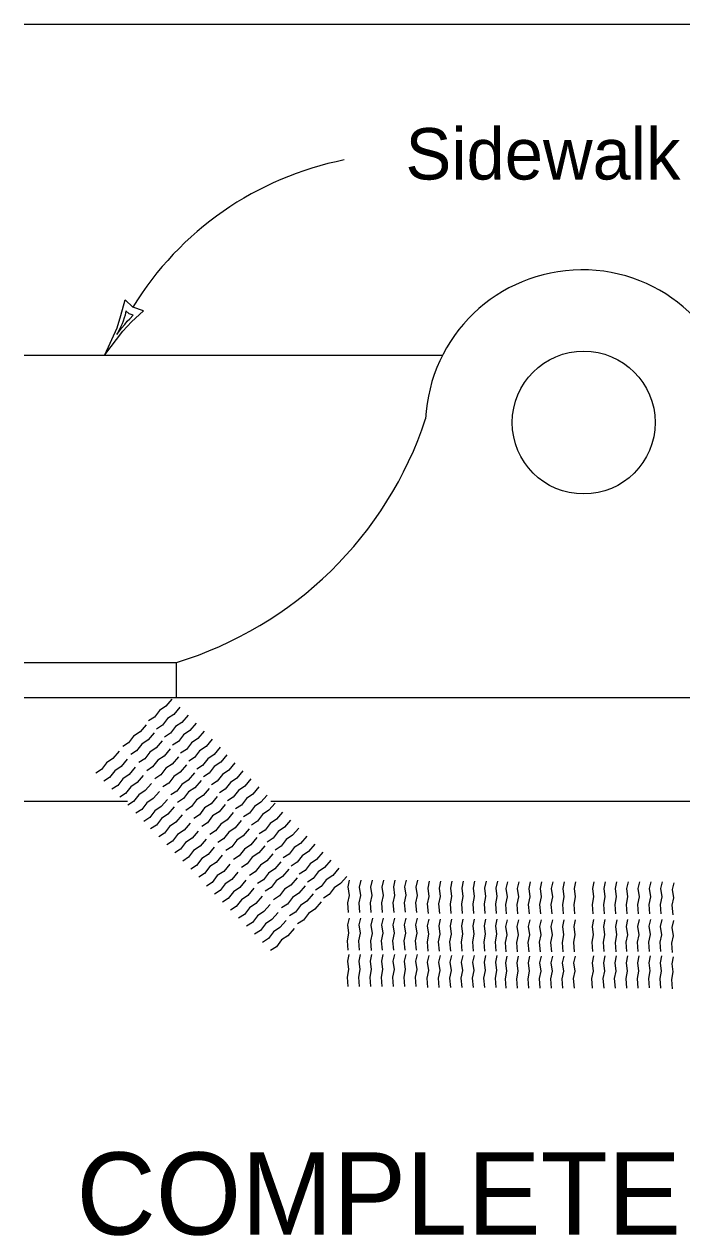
# Model space of a CAD drawing. Extents: x 539344 to 540004, y 1574686 to 1575110.
# Drawn here: x 539790.6 to 539822.6, y 1574749.8 to 1574808.7 of the extents above; entities that cross this region are included whole.
import ezdxf

# ---------------------------------------------------------------- set-up
doc = ezdxf.new("R2010")
doc.units = 0
doc.layers.add('Default', color=7, linetype='Continuous')

msp = doc.modelspace()

# ---------------------------------------------------------------- linework, layer by layer
at = {"layer": 'Default'}
for p, q in [((539790.564, 1574808.736), (539848.567, 1574808.736)), ((539795.852, 1574794.98), (539795.47, 1574795.324)), ((539796.366, 1574794.792), (539795.852, 1574794.98)), ((539790.564, 1574792.644), (539810.928, 1574792.644)), ((539790.564, 1574777.696), (539797.978, 1574777.696)), ((539797.978, 1574775.988), (539797.978, 1574777.696)), ((539790.564, 1574775.988), (539797.978, 1574775.988)), ((539797.978, 1574775.988), (539837.69, 1574775.988)), ((539790.564, 1574770.948), (539795.588, 1574770.948)), ((539802.566, 1574770.948), (539832.96, 1574770.948))]:
    msp.add_line(p, q, dxfattribs=at)
for points in [[(539794.492, 1574792.66), (539795.088, 1574793.974), (539795.272, 1574794.568), (539795.47, 1574795.324)], [(539794.492, 1574792.66), (539795.358, 1574793.814), (539795.792, 1574794.262), (539796.366, 1574794.792)], [(539795.074, 1574793.644), (539795.298, 1574793.954), (539795.456, 1574794.134), (539795.578, 1574794.296), (539795.698, 1574794.408), (539795.866, 1574794.582), (539795.668, 1574794.646), (539795.508, 1574794.794), (539795.478, 1574794.59), (539795.434, 1574794.448), (539795.372, 1574794.3), (539795.328, 1574794.158), (539795.268, 1574794.036), (539795.208, 1574793.89), (539795.074, 1574793.644)], [(539797.752, 1574775.908), (539797.454, 1574775.558), (539797.142, 1574775.35), (539796.896, 1574775.024), (539796.61, 1574774.844)], [(539798.144, 1574775.518), (539797.846, 1574775.166), (539797.536, 1574774.962), (539797.288, 1574774.634), (539797.002, 1574774.454)], [(539798.538, 1574775.128), (539798.238, 1574774.778), (539797.928, 1574774.57), (539797.682, 1574774.244), (539797.396, 1574774.062)], [(539796.5, 1574774.662), (539796.2, 1574774.312), (539795.888, 1574774.106), (539795.64, 1574773.78), (539795.356, 1574773.598)], [(539798.926, 1574774.736), (539798.626, 1574774.384), (539798.316, 1574774.178), (539798.068, 1574773.852), (539797.784, 1574773.672)], [(539796.892, 1574774.274), (539796.592, 1574773.922), (539796.28, 1574773.716), (539796.034, 1574773.39), (539795.75, 1574773.208)], [(539799.318, 1574774.346), (539799.02, 1574773.992), (539798.71, 1574773.788), (539798.46, 1574773.462), (539798.176, 1574773.28)], [(539799.71, 1574773.954), (539799.412, 1574773.602), (539799.1, 1574773.398), (539798.852, 1574773.072), (539798.568, 1574772.89)], [(539795.184, 1574773.372), (539794.884, 1574773.022), (539794.572, 1574772.814), (539794.326, 1574772.488), (539794.042, 1574772.308)], [(539797.282, 1574773.882), (539796.986, 1574773.532), (539796.674, 1574773.324), (539796.426, 1574772.998), (539796.142, 1574772.818)], [(539797.672, 1574773.492), (539797.372, 1574773.14), (539797.06, 1574772.932), (539796.814, 1574772.608), (539796.532, 1574772.426)], [(539800.102, 1574773.564), (539799.802, 1574773.212), (539799.492, 1574773.008), (539799.244, 1574772.68), (539798.96, 1574772.498)], [(539795.576, 1574772.984), (539795.276, 1574772.634), (539794.966, 1574772.426), (539794.718, 1574772.098), (539794.434, 1574771.918)], [(539798.064, 1574773.102), (539797.766, 1574772.75), (539797.454, 1574772.542), (539797.206, 1574772.218), (539796.922, 1574772.036)], [(539798.456, 1574772.71), (539798.156, 1574772.36), (539797.846, 1574772.15), (539797.598, 1574771.826), (539797.314, 1574771.644)], [(539800.426, 1574773.196), (539800.128, 1574772.848), (539799.814, 1574772.638), (539799.568, 1574772.312), (539799.282, 1574772.132)], [(539800.818, 1574772.806), (539800.52, 1574772.456), (539800.208, 1574772.248), (539799.96, 1574771.924), (539799.674, 1574771.74)], [(539795.968, 1574772.592), (539795.672, 1574772.242), (539795.36, 1574772.034), (539795.112, 1574771.708), (539794.826, 1574771.526)], [(539796.358, 1574772.2), (539796.058, 1574771.85), (539795.748, 1574771.644), (539795.5, 1574771.318), (539795.214, 1574771.136)], [(539798.846, 1574772.32), (539798.548, 1574771.968), (539798.238, 1574771.76), (539797.99, 1574771.434), (539797.706, 1574771.252)], [(539801.208, 1574772.416), (539800.91, 1574772.066), (539800.596, 1574771.856), (539800.35, 1574771.532), (539800.064, 1574771.35)], [(539796.75, 1574771.81), (539796.45, 1574771.46), (539796.14, 1574771.254), (539795.89, 1574770.926), (539795.606, 1574770.746)], [(539799.174, 1574771.952), (539798.874, 1574771.6), (539798.562, 1574771.396), (539798.314, 1574771.068), (539798.03, 1574770.886)], [(539799.566, 1574771.562), (539799.266, 1574771.212), (539798.952, 1574771.004), (539798.706, 1574770.678), (539798.422, 1574770.496)], [(539801.598, 1574772.026), (539801.3, 1574771.676), (539800.988, 1574771.466), (539800.74, 1574771.142), (539800.456, 1574770.958)], [(539801.988, 1574771.634), (539801.692, 1574771.284), (539801.38, 1574771.074), (539801.13, 1574770.75), (539800.848, 1574770.568)], [(539797.142, 1574771.418), (539796.844, 1574771.07), (539796.532, 1574770.862), (539796.282, 1574770.536), (539795.998, 1574770.354)], [(539797.534, 1574771.028), (539797.236, 1574770.678), (539796.924, 1574770.47), (539796.674, 1574770.144), (539796.39, 1574769.962)], [(539799.954, 1574771.172), (539799.656, 1574770.818), (539799.344, 1574770.614), (539799.096, 1574770.286), (539798.812, 1574770.104)], [(539802.382, 1574771.242), (539802.084, 1574770.892), (539801.77, 1574770.682), (539801.524, 1574770.358), (539801.238, 1574770.176)], [(539797.858, 1574770.662), (539797.56, 1574770.312), (539797.248, 1574770.104), (539797, 1574769.778), (539796.714, 1574769.596)], [(539800.344, 1574770.782), (539800.046, 1574770.428), (539799.734, 1574770.224), (539799.486, 1574769.896), (539799.202, 1574769.714)], [(539800.736, 1574770.39), (539800.438, 1574770.036), (539800.126, 1574769.832), (539799.878, 1574769.504), (539799.594, 1574769.324)], [(539802.772, 1574770.852), (539802.472, 1574770.502), (539802.16, 1574770.292), (539801.912, 1574769.968), (539801.628, 1574769.784)], [(539803.14, 1574770.416), (539802.84, 1574770.064), (539802.53, 1574769.858), (539802.284, 1574769.532), (539801.998, 1574769.35)], [(539798.25, 1574770.272), (539797.95, 1574769.92), (539797.64, 1574769.714), (539797.392, 1574769.388), (539797.108, 1574769.208)], [(539798.638, 1574769.88), (539798.342, 1574769.528), (539798.03, 1574769.322), (539797.782, 1574768.996), (539797.498, 1574768.814)], [(539801.128, 1574769.998), (539800.83, 1574769.644), (539800.518, 1574769.44), (539800.27, 1574769.112), (539799.986, 1574768.93)], [(539803.53, 1574770.024), (539803.228, 1574769.672), (539802.92, 1574769.466), (539802.674, 1574769.14), (539802.386, 1574768.958)], [(539799.03, 1574769.49), (539798.732, 1574769.138), (539798.42, 1574768.932), (539798.172, 1574768.606), (539797.886, 1574768.426)], [(539801.516, 1574769.606), (539801.218, 1574769.256), (539800.906, 1574769.048), (539800.66, 1574768.722), (539800.374, 1574768.542)], [(539803.922, 1574769.632), (539803.62, 1574769.284), (539803.31, 1574769.076), (539803.062, 1574768.752), (539802.776, 1574768.568)], [(539804.312, 1574769.244), (539804.012, 1574768.892), (539803.702, 1574768.686), (539803.456, 1574768.36), (539803.17, 1574768.18)], [(539799.422, 1574769.098), (539799.122, 1574768.748), (539798.81, 1574768.54), (539798.564, 1574768.216), (539798.278, 1574768.034)], [(539799.814, 1574768.706), (539799.516, 1574768.356), (539799.204, 1574768.148), (539798.956, 1574767.822), (539798.67, 1574767.64)], [(539801.886, 1574769.17), (539801.59, 1574768.82), (539801.276, 1574768.612), (539801.03, 1574768.286), (539800.744, 1574768.104)], [(539802.274, 1574768.778), (539801.976, 1574768.426), (539801.662, 1574768.22), (539801.416, 1574767.894), (539801.132, 1574767.714)], [(539804.704, 1574768.852), (539804.404, 1574768.5), (539804.094, 1574768.292), (539803.846, 1574767.97), (539803.562, 1574767.786)], [(539800.202, 1574768.316), (539799.902, 1574767.964), (539799.59, 1574767.76), (539799.344, 1574767.432), (539799.06, 1574767.25)], [(539802.666, 1574768.39), (539802.366, 1574768.038), (539802.056, 1574767.832), (539801.808, 1574767.504), (539801.524, 1574767.322)], [(539803.056, 1574767.998), (539802.76, 1574767.65), (539802.448, 1574767.44), (539802.202, 1574767.114), (539801.916, 1574766.932)], [(539805.096, 1574768.46), (539804.796, 1574768.11), (539804.486, 1574767.902), (539804.238, 1574767.578), (539803.952, 1574767.396)], [(539805.484, 1574768.07), (539805.184, 1574767.718), (539804.874, 1574767.512), (539804.626, 1574767.188), (539804.342, 1574767.004)], [(539800.572, 1574767.88), (539800.274, 1574767.53), (539799.96, 1574767.322), (539799.714, 1574766.996), (539799.428, 1574766.814)], [(539800.958, 1574767.488), (539800.662, 1574767.138), (539800.35, 1574766.93), (539800.102, 1574766.604), (539799.818, 1574766.422)], [(539803.434, 1574767.634), (539803.136, 1574767.284), (539802.822, 1574767.076), (539802.576, 1574766.75), (539802.292, 1574766.568)], [(539805.876, 1574767.678), (539805.576, 1574767.326), (539805.266, 1574767.118), (539805.018, 1574766.796), (539804.732, 1574766.614)], [(539801.352, 1574767.1), (539801.054, 1574766.748), (539800.742, 1574766.54), (539800.492, 1574766.214), (539800.208, 1574766.032)], [(539803.84, 1574767.216), (539803.542, 1574766.866), (539803.23, 1574766.658), (539802.984, 1574766.332), (539802.698, 1574766.148)], [(539804.23, 1574766.824), (539803.93, 1574766.474), (539803.62, 1574766.266), (539803.372, 1574765.938), (539803.088, 1574765.758)], [(539806.264, 1574767.286), (539805.964, 1574766.936), (539805.654, 1574766.73), (539805.406, 1574766.404), (539805.122, 1574766.22)], [(539806.348, 1574765.536), (539806.312, 1574765.996), (539806.386, 1574766.362), (539806.33, 1574766.77), (539806.402, 1574767.098)], [(539806.902, 1574765.534), (539806.864, 1574765.994), (539806.938, 1574766.362), (539806.884, 1574766.766), (539806.956, 1574767.098)], [(539807.454, 1574765.534), (539807.416, 1574765.994), (539807.492, 1574766.362), (539807.436, 1574766.766), (539807.51, 1574767.098)], [(539808.008, 1574765.534), (539807.97, 1574765.994), (539808.044, 1574766.362), (539807.99, 1574766.766), (539808.062, 1574767.098)], [(539808.562, 1574765.536), (539808.524, 1574765.996), (539808.598, 1574766.362), (539808.544, 1574766.77), (539808.616, 1574767.098)], [(539809.114, 1574765.54), (539809.076, 1574765.996), (539809.15, 1574766.364), (539809.094, 1574766.77), (539809.168, 1574767.1)], [(539809.664, 1574765.534), (539809.628, 1574765.994), (539809.702, 1574766.362), (539809.646, 1574766.766), (539809.72, 1574767.098)], [(539810.234, 1574765.488), (539810.198, 1574765.95), (539810.274, 1574766.314), (539810.216, 1574766.72), (539810.29, 1574767.05)], [(539810.786, 1574765.488), (539810.748, 1574765.946), (539810.822, 1574766.314), (539810.766, 1574766.718), (539810.84, 1574767.048)], [(539811.34, 1574765.488), (539811.304, 1574765.946), (539811.378, 1574766.314), (539811.322, 1574766.718), (539811.396, 1574767.048)], [(539811.894, 1574765.488), (539811.856, 1574765.946), (539811.93, 1574766.314), (539811.876, 1574766.718), (539811.95, 1574767.048)], [(539812.446, 1574765.488), (539812.408, 1574765.946), (539812.482, 1574766.314), (539812.426, 1574766.718), (539812.5, 1574767.048)], [(539813, 1574765.486), (539812.962, 1574765.946), (539813.036, 1574766.312), (539812.98, 1574766.718), (539813.054, 1574767.046)], [(539813.552, 1574765.488), (539813.514, 1574765.946), (539813.588, 1574766.314), (539813.532, 1574766.718), (539813.606, 1574767.048)], [(539814.04, 1574765.458), (539814.004, 1574765.916), (539814.076, 1574766.284), (539814.022, 1574766.69), (539814.094, 1574767.02)], [(539814.592, 1574765.458), (539814.558, 1574765.916), (539814.63, 1574766.284), (539814.576, 1574766.69), (539814.648, 1574767.02)], [(539815.146, 1574765.46), (539815.112, 1574765.918), (539815.184, 1574766.284), (539815.13, 1574766.692), (539815.202, 1574767.02)], [(539815.7, 1574765.46), (539815.664, 1574765.92), (539815.738, 1574766.286), (539815.682, 1574766.692), (539815.756, 1574767.02)], [(539816.252, 1574765.458), (539816.214, 1574765.916), (539816.288, 1574766.284), (539816.232, 1574766.69), (539816.306, 1574767.02)], [(539816.806, 1574765.46), (539816.77, 1574765.918), (539816.844, 1574766.284), (539816.786, 1574766.692), (539816.86, 1574767.02)], [(539817.358, 1574765.462), (539817.322, 1574765.922), (539817.396, 1574766.288), (539817.34, 1574766.692), (539817.414, 1574767.022)], [(539818.252, 1574765.464), (539818.214, 1574765.924), (539818.29, 1574766.292), (539818.234, 1574766.698), (539818.306, 1574767.028)], [(539818.804, 1574765.464), (539818.768, 1574765.924), (539818.84, 1574766.292), (539818.786, 1574766.696), (539818.858, 1574767.028)], [(539819.358, 1574765.464), (539819.32, 1574765.924), (539819.394, 1574766.292), (539819.34, 1574766.696), (539819.412, 1574767.028)], [(539819.912, 1574765.464), (539819.874, 1574765.924), (539819.946, 1574766.292), (539819.894, 1574766.696), (539819.966, 1574767.028)], [(539820.466, 1574765.464), (539820.428, 1574765.924), (539820.5, 1574766.292), (539820.448, 1574766.698), (539820.518, 1574767.028)], [(539821.018, 1574765.468), (539820.98, 1574765.926), (539821.054, 1574766.292), (539820.998, 1574766.698), (539821.07, 1574767.028)], [(539821.568, 1574765.464), (539821.532, 1574765.924), (539821.606, 1574766.292), (539821.55, 1574766.696), (539821.624, 1574767.028)], [(539822.138, 1574765.418), (539822.1, 1574765.878), (539822.176, 1574766.244), (539822.12, 1574766.648), (539822.192, 1574766.98)], [(539801.744, 1574766.71), (539801.446, 1574766.356), (539801.134, 1574766.148), (539800.886, 1574765.826), (539800.6, 1574765.642)], [(539802.136, 1574766.318), (539801.838, 1574765.966), (539801.524, 1574765.758), (539801.278, 1574765.434), (539800.99, 1574765.25)], [(539804.62, 1574766.432), (539804.322, 1574766.084), (539804.01, 1574765.876), (539803.764, 1574765.55), (539803.478, 1574765.366)], [(539802.526, 1574765.926), (539802.228, 1574765.574), (539801.916, 1574765.366), (539801.668, 1574765.042), (539801.382, 1574764.858)], [(539805.01, 1574766.042), (539804.71, 1574765.69), (539804.4, 1574765.484), (539804.152, 1574765.156), (539803.868, 1574764.976)], [(539802.916, 1574765.534), (539802.618, 1574765.184), (539802.306, 1574764.976), (539802.058, 1574764.65), (539801.774, 1574764.468)], [(539803.306, 1574765.144), (539803.008, 1574764.792), (539802.696, 1574764.584), (539802.448, 1574764.26), (539802.162, 1574764.076)], [(539806.332, 1574763.694), (539806.296, 1574764.154), (539806.368, 1574764.52), (539806.312, 1574764.928), (539806.386, 1574765.256)], [(539806.884, 1574763.694), (539806.848, 1574764.152), (539806.922, 1574764.52), (539806.866, 1574764.924), (539806.938, 1574765.256)], [(539807.466, 1574763.686), (539807.43, 1574764.144), (539807.506, 1574764.512), (539807.448, 1574764.916), (539807.522, 1574765.246)], [(539807.992, 1574763.694), (539807.956, 1574764.152), (539808.028, 1574764.52), (539807.972, 1574764.924), (539808.044, 1574765.256)], [(539808.546, 1574763.694), (539808.508, 1574764.154), (539808.582, 1574764.52), (539808.526, 1574764.928), (539808.598, 1574765.256)], [(539809.096, 1574763.696), (539809.058, 1574764.156), (539809.134, 1574764.524), (539809.078, 1574764.928), (539809.15, 1574765.256)], [(539809.648, 1574763.694), (539809.61, 1574764.152), (539809.686, 1574764.52), (539809.63, 1574764.924), (539809.702, 1574765.256)], [(539810.218, 1574763.646), (539810.182, 1574764.106), (539810.256, 1574764.474), (539810.198, 1574764.878), (539810.274, 1574765.208)], [(539810.768, 1574763.644), (539810.73, 1574764.104), (539810.806, 1574764.47), (539810.75, 1574764.878), (539810.822, 1574765.206)], [(539811.324, 1574763.644), (539811.284, 1574764.104), (539811.36, 1574764.47), (539811.304, 1574764.878), (539811.378, 1574765.206)], [(539811.878, 1574763.644), (539811.838, 1574764.104), (539811.914, 1574764.47), (539811.858, 1574764.878), (539811.93, 1574765.206)], [(539812.43, 1574763.644), (539812.39, 1574764.104), (539812.468, 1574764.47), (539812.41, 1574764.878), (539812.482, 1574765.206)], [(539812.98, 1574763.644), (539812.944, 1574764.102), (539813.02, 1574764.47), (539812.962, 1574764.876), (539813.036, 1574765.206)], [(539813.534, 1574763.644), (539813.496, 1574764.104), (539813.572, 1574764.47), (539813.516, 1574764.878), (539813.588, 1574765.206)], [(539814.024, 1574763.616), (539813.986, 1574764.076), (539814.06, 1574764.442), (539814.004, 1574764.848), (539814.076, 1574765.176)], [(539814.576, 1574763.616), (539814.54, 1574764.076), (539814.612, 1574764.442), (539814.558, 1574764.848), (539814.63, 1574765.176)], [(539815.13, 1574763.616), (539815.094, 1574764.076), (539815.166, 1574764.444), (539815.112, 1574764.848), (539815.184, 1574765.178)], [(539815.684, 1574763.618), (539815.648, 1574764.078), (539815.72, 1574764.446), (539815.664, 1574764.85), (539815.738, 1574765.178)], [(539816.236, 1574763.616), (539816.198, 1574764.076), (539816.272, 1574764.442), (539816.216, 1574764.848), (539816.288, 1574765.176)], [(539816.788, 1574763.616), (539816.752, 1574764.076), (539816.826, 1574764.444), (539816.77, 1574764.848), (539816.844, 1574765.178)], [(539817.34, 1574763.618), (539817.306, 1574764.078), (539817.38, 1574764.446), (539817.324, 1574764.852), (539817.396, 1574765.18)], [(539818.234, 1574763.624), (539818.198, 1574764.084), (539818.272, 1574764.45), (539818.216, 1574764.856), (539818.29, 1574765.186)], [(539818.788, 1574763.624), (539818.752, 1574764.08), (539818.824, 1574764.448), (539818.768, 1574764.854), (539818.84, 1574765.184)], [(539819.37, 1574763.614), (539819.334, 1574764.072), (539819.408, 1574764.44), (539819.352, 1574764.846), (539819.424, 1574765.176)], [(539819.896, 1574763.624), (539819.858, 1574764.08), (539819.932, 1574764.448), (539819.874, 1574764.854), (539819.946, 1574765.184)], [(539820.448, 1574763.624), (539820.412, 1574764.084), (539820.484, 1574764.45), (539820.428, 1574764.856), (539820.5, 1574765.186)], [(539821, 1574763.624), (539820.962, 1574764.086), (539821.038, 1574764.452), (539820.98, 1574764.858), (539821.054, 1574765.186)], [(539821.55, 1574763.624), (539821.514, 1574764.08), (539821.588, 1574764.448), (539821.532, 1574764.854), (539821.606, 1574765.184)], [(539822.12, 1574763.576), (539822.084, 1574764.034), (539822.158, 1574764.402), (539822.102, 1574764.806), (539822.176, 1574765.136)], [(539803.696, 1574764.752), (539803.398, 1574764.4), (539803.086, 1574764.194), (539802.838, 1574763.866), (539802.554, 1574763.684)], [(539806.326, 1574761.928), (539806.29, 1574762.388), (539806.364, 1574762.754), (539806.308, 1574763.158), (539806.38, 1574763.49)], [(539806.876, 1574761.926), (539806.842, 1574762.386), (539806.914, 1574762.752), (539806.86, 1574763.156), (539806.932, 1574763.486)], [(539807.43, 1574761.926), (539807.394, 1574762.386), (539807.466, 1574762.752), (539807.414, 1574763.156), (539807.484, 1574763.486)], [(539807.984, 1574761.926), (539807.948, 1574762.386), (539808.022, 1574762.752), (539807.966, 1574763.156), (539808.04, 1574763.486)], [(539808.536, 1574761.928), (539808.502, 1574762.388), (539808.576, 1574762.754), (539808.52, 1574763.158), (539808.594, 1574763.49)], [(539809.09, 1574761.928), (539809.054, 1574762.39), (539809.126, 1574762.754), (539809.07, 1574763.158), (539809.144, 1574763.49)], [(539809.642, 1574761.926), (539809.606, 1574762.386), (539809.68, 1574762.752), (539809.624, 1574763.156), (539809.696, 1574763.486)], [(539810.212, 1574761.878), (539810.174, 1574762.338), (539810.248, 1574762.706), (539810.194, 1574763.112), (539810.266, 1574763.442)], [(539810.762, 1574761.878), (539810.726, 1574762.336), (539810.8, 1574762.706), (539810.744, 1574763.11), (539810.818, 1574763.44)], [(539811.318, 1574761.878), (539811.28, 1574762.336), (539811.352, 1574762.706), (539811.3, 1574763.11), (539811.37, 1574763.44)], [(539811.872, 1574761.878), (539811.834, 1574762.336), (539811.906, 1574762.706), (539811.852, 1574763.11), (539811.924, 1574763.44)], [(539812.424, 1574761.878), (539812.386, 1574762.336), (539812.46, 1574762.706), (539812.404, 1574763.11), (539812.478, 1574763.44)], [(539812.974, 1574761.878), (539812.938, 1574762.336), (539813.012, 1574762.704), (539812.956, 1574763.108), (539813.03, 1574763.44)], [(539813.528, 1574761.878), (539813.492, 1574762.336), (539813.566, 1574762.706), (539813.508, 1574763.11), (539813.584, 1574763.44)], [(539814.016, 1574761.85), (539813.98, 1574762.308), (539814.054, 1574762.674), (539813.998, 1574763.08), (539814.072, 1574763.41)], [(539814.57, 1574761.85), (539814.532, 1574762.308), (539814.608, 1574762.674), (539814.552, 1574763.08), (539814.626, 1574763.41)], [(539815.124, 1574761.85), (539815.086, 1574762.31), (539815.16, 1574762.674), (539815.106, 1574763.082), (539815.178, 1574763.41)], [(539815.678, 1574761.852), (539815.64, 1574762.312), (539815.714, 1574762.678), (539815.658, 1574763.082), (539815.732, 1574763.412)], [(539816.228, 1574761.85), (539816.192, 1574762.308), (539816.266, 1574762.674), (539816.208, 1574763.08), (539816.284, 1574763.41)], [(539816.782, 1574761.85), (539816.746, 1574762.31), (539816.82, 1574762.674), (539816.764, 1574763.082), (539816.838, 1574763.41)], [(539817.336, 1574761.852), (539817.298, 1574762.312), (539817.372, 1574762.68), (539817.316, 1574763.084), (539817.39, 1574763.412)], [(539818.228, 1574761.856), (539818.192, 1574762.316), (539818.266, 1574762.682), (539818.212, 1574763.086), (539818.284, 1574763.418)], [(539818.78, 1574761.854), (539818.744, 1574762.316), (539818.816, 1574762.682), (539818.764, 1574763.086), (539818.836, 1574763.416)], [(539819.334, 1574761.854), (539819.296, 1574762.316), (539819.37, 1574762.682), (539819.316, 1574763.086), (539819.388, 1574763.416)], [(539819.888, 1574761.854), (539819.852, 1574762.316), (539819.924, 1574762.682), (539819.87, 1574763.086), (539819.942, 1574763.416)], [(539820.44, 1574761.856), (539820.406, 1574762.316), (539820.478, 1574762.682), (539820.424, 1574763.086), (539820.496, 1574763.418)], [(539820.992, 1574761.858), (539820.956, 1574762.318), (539821.03, 1574762.684), (539820.974, 1574763.088), (539821.048, 1574763.42)], [(539821.546, 1574761.854), (539821.51, 1574762.316), (539821.582, 1574762.682), (539821.526, 1574763.086), (539821.6, 1574763.416)], [(539822.114, 1574761.808), (539822.078, 1574762.266), (539822.15, 1574762.636), (539822.096, 1574763.04), (539822.168, 1574763.37)]]:
    msp.add_lwpolyline(points, dxfattribs=at)
msp.add_circle((539817.792, 1574789.362), 3.476, dxfattribs=at)
for centre, radius, start, end in [((539809.161, 1574786.812), 15.616, 101.15963, 148.45967), ((539817.714, 1574789.164), 7.627, 3.77239, 177.19831), ((539792.624, 1574795.298), 18.398, 286.91961, 341.75077)]:
    msp.add_arc(centre, radius, start, end, dxfattribs=at)

# ---------------------------------------------------------------- texts
for s, height, p in [('Sidewalk', 2.5, (539809.119, 1574801.183)), ('COMPLETED  INLET', 4, (539793.103, 1574749.861))]:
    msp.add_text(s, height=height, dxfattribs=at).set_placement(p)

doc.saveas('drawing.dxf')
